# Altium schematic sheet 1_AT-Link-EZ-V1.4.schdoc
size 307 x 218 mm; Symbol: Artery_A4; Device: Artery_A4; @Project Name: AT-START-M416; @Page Count: 4; @Create Date: 2024-11-11; Company: Artery Technology; Drawed: SD; Version: 1.1; Page Size: A4; @Update Date: 2024-12-31; @Page No: 1; @Schematic Name: AT-START-M416-V1.1; @Page Name: AT-Link-EZ-V1.4; Title Block Position: 3; Width: 1170; Height: 825; Region Start: 1; X Region Count: 6; Y Region Count: 4; Blade Width: 10; @Board Name: AT-START-M416-V1.1; @Create Time: 14:16:05; @Update Time: 17:37:58
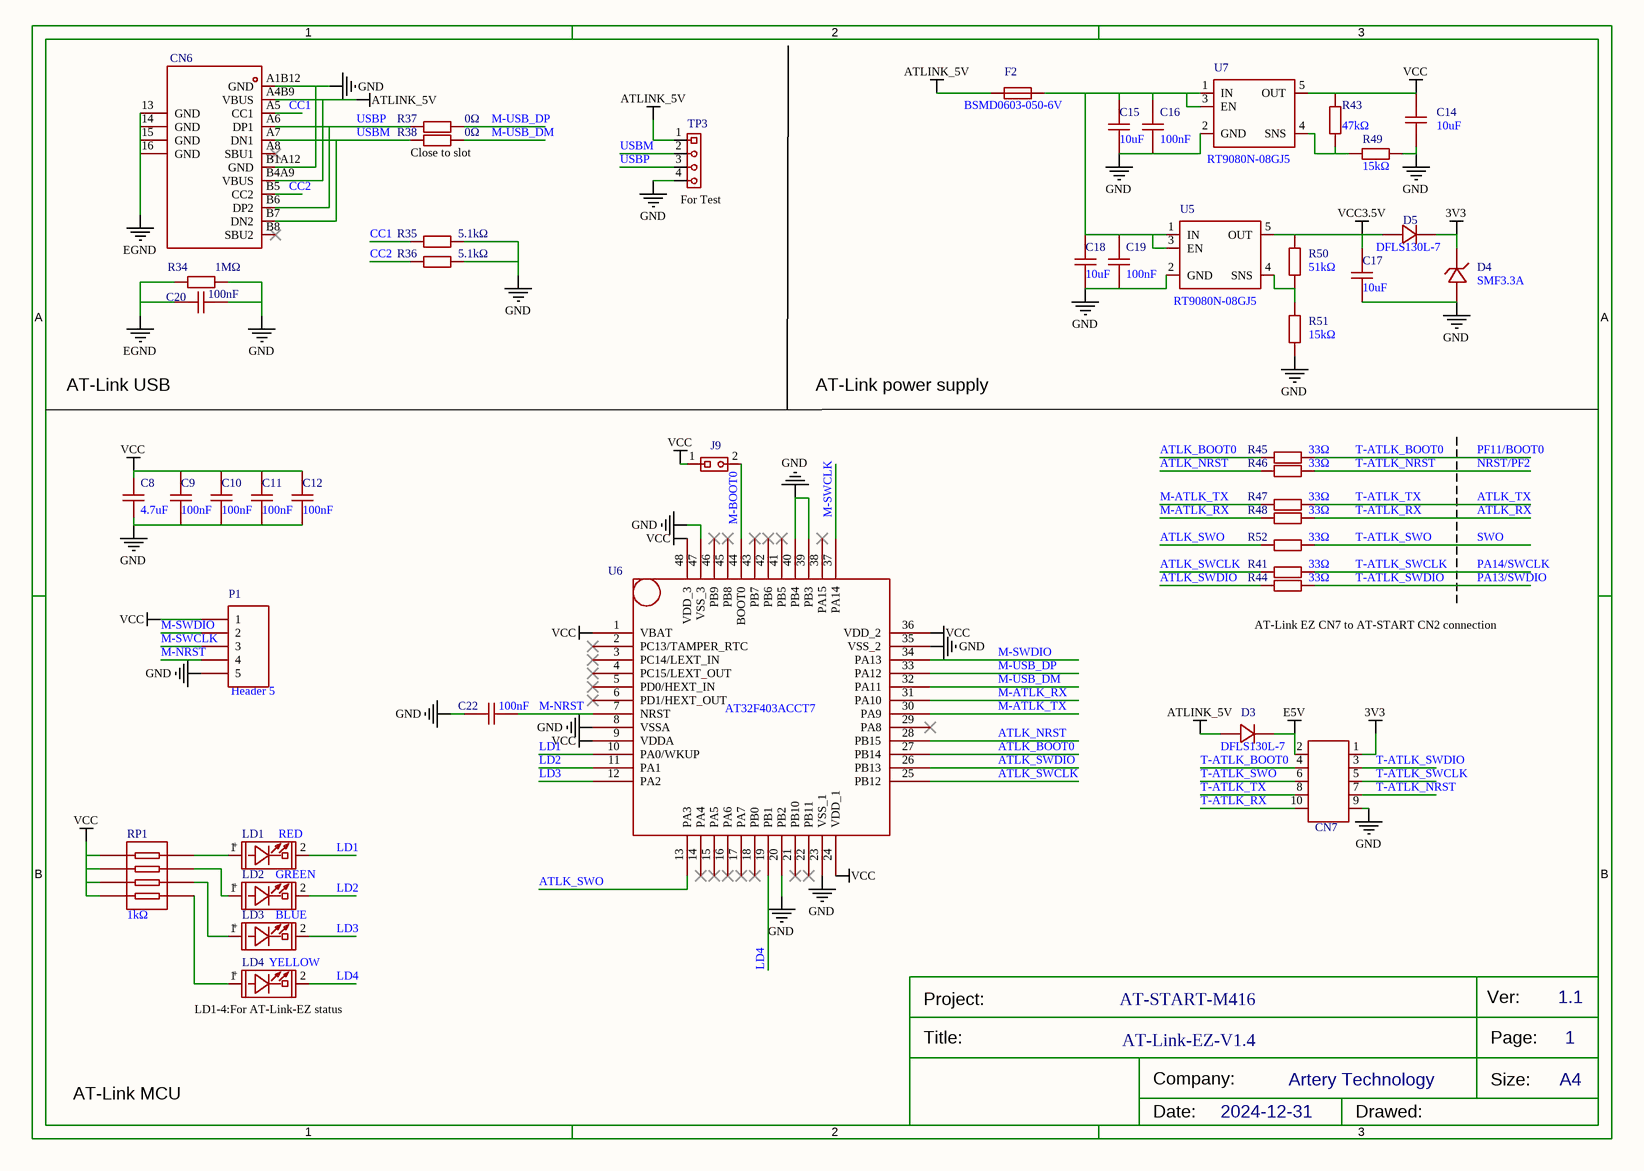
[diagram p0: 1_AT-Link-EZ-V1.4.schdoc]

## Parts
C8  4.7uF  [C0603]
C9  100nF  [C0603]
C10  100nF  [C0603]
C11  100nF  [C0603]
C12  100nF  [C0603]
C14  10uF  [C0603]
C15  10uF  [C0603]
C16  100nF  [C0603]
C17  10uF  [C0603]
C18  10uF  [C0603]
C19  100nF  [C0603]
C20  value 100nF  [C0603]
C22  100nF  [C0603]
CN6  (no value)  [USB-C-SMD_TYPEC-304-BCP16]
CN7  CON10  [HDR2X5]  (value not drawn)
D3  DFLS130L-7  [POWERDI-123_L2.8-W1.8-LS3.7-RD]
D4  SMF3.3A  [SOD-123FL_L2.8-W1.8-LS3.8-RD]
D5  DFLS130L-7  [POWERDI-123_L2.8-W1.8-LS3.7-RD]
F2  BSMD0603-050-6V  [F0603]
J9  1X2P_2.54M  [HDR1X2]  (value not drawn)
LD1  RED  [LED0603]
LD2  GREEN  [LED0603]
LD3  BLUE  [LED0603]
LD4  YELLOW  [LED0603]
P1  Header 5  [HDR1X5]
R34  value 1MΩ  [R0603]
R35  value 5.1kΩ  [R0603]
R36  value 5.1kΩ  [R0603]
R37  value 0Ω  [R0603]
R38  value 0Ω  [R0603]
R41  33Ω  [R0603]
R43  47kΩ  [R0603]
R44  33Ω  [R0603]
R45  33Ω  [R0603]
R46  33Ω  [R0603]
R47  33Ω  [R0603]
R48  33Ω  [R0603]
R49  15kΩ  [R0603]
R50  51kΩ  [R0603]
R51  15kΩ  [R0603]
R52  33Ω  [R0603]
RP1  1kΩ  [RES-ARRAY-SMD_0603-8P-L3.2-W1.6-BL]
TP3  1X4P_2.54F  [HDR1X4 - TOP]  (value not drawn)
U5  RT9080N-08GJ5  [SOT-23-5]
U6  AT32F403ACCT7  [LQFP48 - 2]
U7  RT9080N-08GJ5  [SOT-23-5]

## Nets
3V3: CN7.1 D4.1(C) D5.1
ATLINK_5V: CN6.A4B9(VBUS) CN6.B4A9(VBUS) D3.2 F2.1 TP3.1
E5V: CN7.2 D3.1
EGND: C20.2 CN6.13(GND) CN6.14(GND) CN6.15(GND) CN6.16(GND) R34.1
GND: C8.1 C9.1 C10.1 C11.1 C12.1 C14.1 C15.1 C16.1 C17.1 C18.1 C19.1 C20.1 C22.1 CN6.A1B12(GND) CN6.B1A12(GND) CN7.9 D4.2(A) P1.5 R34.2 R35.2 R36.2 R49.2 R51.2 TP3.4 U5.2(GND) U6.8(VSSA) U6.20(PB2) U6.23(VSS_1) U6.35(VSS_2) U6.39(PB3) U6.40(PB4) U6.47(VSS_3) U7.2(GND)
VCC: C8.2 C9.2 C10.2 C11.2 C12.2 C14.2 J9.1 P1.1 R43.1 RP1.1 RP1.2 RP1.3 RP1.4 U6.1(VBAT) U6.9(VDDA) U6.24(VDD_1) U6.36(VDD_2) U6.48(VDD_3) U7.5(OUT)
VCC3.5V: C17.2 D5.2 R50.1 U5.5(OUT)
ATLK_BOOT0: R45.1 U6.27(PB14)
ATLK_NRST: R46.1 U6.28(PB15)
ATLK_RX: CN7.10 R48.2  [also labelled T-ATLK_RX]
ATLK_SWCLK: R41.1 U6.25(PB12)
ATLK_SWDIO: R44.1 U6.26(PB13)
ATLK_SWO: R52.1 U6.13(PA3)
ATLK_TX: CN7.8 R47.2  [also labelled T-ATLK_TX]
CC1: CN6.A5(CC1) R35.1
CC2: CN6.B5(CC2) R36.1
LD1: LD1.2(CATHODE) U6.10(PA0/WKUP)
LD2: LD2.2(CATHODE) U6.11(PA1)
LD3: LD3.2(CATHODE) U6.12(PA2)
LD4: LD4.2(CATHODE) U6.19(PB1)
M-ATLK_RX: R48.1 U6.31(PA10)
M-ATLK_TX: R47.1 U6.30(PA9)
M-BOOT0: J9.2 U6.44(BOOT0)
M-NRST: C22.2 P1.4 U6.7(NRST)
M-SWCLK: P1.3 U6.37(PA14)
M-SWDIO: P1.2 U6.34(PA13)
M-USB_DM: R38.2 U6.32(PA11)
M-USB_DP: R37.2 U6.33(PA12)
NRST/PF2: CN7.7 R46.2  [also labelled T-ATLK_NRST]
PA13/SWDIO: CN7.3 R44.2  [also labelled T-ATLK_SWDIO]
PA14/SWCLK: CN7.5 R41.2  [also labelled T-ATLK_SWCLK]
PF11/BOOT0: CN7.4 R45.2  [also labelled T-ATLK_BOOT0]
SWO: CN7.6 R52.2  [also labelled T-ATLK_SWO]
USBM: CN6.A7(DN1) CN6.B7(DN2) R38.1 TP3.2
USBP: CN6.A6(DP1) CN6.B6(DP2) R37.1 TP3.3
NetC15_2: C15.2 C16.2 C18.2 C19.2 F2.2 U5.1(IN) U5.3(EN) U7.1(IN) U7.3(EN)
NetLD1_1: LD1.1(ANODE) RP1.8
NetLD2_1: LD2.1(ANODE) RP1.7
NetLD3_1: LD3.1(ANODE) RP1.6
NetLD4_1: LD4.1(ANODE) RP1.5
NetR43_2: R43.2 R49.1 U7.4(SNS)
NetR50_2: R50.2 R51.1 U5.4(SNS)

Not connected (* = marked no-connect by the designer): CN6 A8(SBU1)* B8(SBU2)*; U6 2(PC13/TAMPER_RTC)* 3(PC14/LEXT_IN)* 4(PC15/LEXT_OUT)* 5(PD0/HEXT_IN)* 6(PD1/HEXT_OUT)* 14(PA4)* 15(PA5)* 16(PA6)* 17(PA7)* 18(PB0)* 21(PB10)* 22(PB11)* 29(PA8)* 38(PA15)* 41(PB5)* 42(PB6)* 43(PB7)* 45(PB8)* 46(PB9)*

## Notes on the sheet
- (near R38) Close to slot
- (near TP3) For Test
- AT-Link USB
- AT-Link power supply
- AT-Link EZ CN7 to AT-START CN2 connection
- (near LD4) LD1-4:For AT-Link-EZ status
- AT-START-M416
- AT-Link MCU

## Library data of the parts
C8 = CL10A475KO8NNNC: Manufacturer: SAMSUNG(三星); Add into BOM: yes; Tolerance: ±10%; Voltage Rated: 16V; Temperature Coefficient: X5R; Origin Footprint 2: 0603; Origin Footprint 3: 0402; Origin Footprint 4: C2512; Origin Footprint 5: 1608[0603]; Origin Footprint 6: C1210
C9-C12 = CC0603KRX7R9BB104: Manufacturer: YAGEO(国巨); Add into BOM: yes; Tolerance: ±10%; Voltage Rated: 50V; Temperature Coefficient: X7R; Origin Footprint 2: 0603; Origin Footprint 3: 0402; Origin Footprint 4: C2512; Origin Footprint 5: 1608[0603]; Origin Footprint 6: C1210
C14 C15 C17 C18 = CL10A106KP8NNNC: Manufacturer: SAMSUNG(三星); Add into BOM: yes; Tolerance: ±10%; Voltage Rated: 10V; Temperature Coefficient: X5R
C16 C19 C20 C22 = CC0603KRX7R9BB104: Manufacturer: YAGEO(国巨); Add into BOM: yes; Tolerance: ±10%; Voltage Rated: 50V; Temperature Coefficient: X7R
CN6 = TYPEC-304-BCP16: Manufacturer: XUNPU(讯普); Add into BOM: yes; Connector Type: Type-C; Gender: 母座; Number of Contacts: 16.0; Number of Ports: 1; Mounting Sytle: 卧贴; Current Rating - Power (Max): 3A; Welding Temperature (Max): 260
CN7 = CON10: Symbol: CON10A_0; Add into BOM: yes
D3 D5 = DFLS130L-7: Manufacturer: DIODES(美台); Add into BOM: yes; Forward Voltage (Vf@If): 310mV@1A; Reverse Voltage (Vr): 30V; Average Rectified Current (Io): 1A; Origin Footprint: SOD-123
D4 = SMF3.3A_C2759873: Manufacturer: Leiditech(雷卯电子); Add into BOM: yes; Reverse Stand-Off Voltage (Vrwm): 3.3V; Maximum Clamping Voltage: 7.3V; Peak Pulse Current (Ipp)@10/1000us: 27.5A; Breakdown Voltage: 4.1V; Reverse Leakage Current (Ir): 500uA; Type: TVS; Origin Footprint: SOD-123
F2 = BSMD0603-050-6V: Manufacturer: BHFUSE(佰宏); Add into BOM: yes; Operating Voltage (Max): 6V; Current Rating (Max): 40A; Hold Current: 500mA; Trip Current: 1A; Power Dissipation: 500mW; Resistance - Initial (Ri) (Min): 100mΩ; Resistance - Post Trip (R1) (Max): 800mΩ; Maximum Time to Trip: 100ms; Origin Footprint: r0603
J9 = 1X2P_2.54M: Symbol: 1X2P,Male,DIP_2.54; Origin Footprint 2: SIP_2P; Add into BOM: yes; Check: true
LD1 = RED: Symbol: RED,SMD0603; Add into BOM: yes
LD2 = GREEN: Symbol: GREEN,SMD0603; Add into BOM: yes
LD3 = BLUE: Symbol: BLUE,SMD0603; Add into BOM: yes
LD4 = YELLOW: Symbol: YELLOW,SMD0603; Add into BOM: yes
P1 = Header 5: Add into BOM: yes
R34 = RC0603FR-071ML: Manufacturer: YAGEO(国巨); Add into BOM: yes; Tolerance: ±1%; Power(Watts): 100mW; Temperature Coefficient: ±100ppm/; Overload Voltage (Max): 75V
R35 R36 = 0603WAF5101T5E: Manufacturer: UNI-ROYAL(厚声); Add into BOM: yes; Tolerance: ±1%; Power(Watts): 1/10W; Temperature Coefficient: ±100ppm/; Overload Voltage (Max): 75V
R37 R38 = 0603WAF0000T5E: Manufacturer: UNI-ROYAL(厚声); Add into BOM: yes; Tolerance: ±1%; Power(Watts): 1/10W; Overload Voltage (Max): 75V
R41 R44-R48 R52 = 0603WAF330JT5E: Manufacturer: UNI-ROYAL(厚声); Add into BOM: yes; Tolerance: ±1%; Power(Watts): 100mW; Overload Voltage (Max): 75V; Temperature Coefficient: ±100ppm/℃
R43 = 0603WAF4702T5E: Manufacturer: UNI-ROYAL(厚声); Add into BOM: yes; Tolerance: ±1%; Power(Watts): 100mW; Overload Voltage (Max): 75V; Temperature Coefficient: ±100ppm/℃
R49 R51 = 0603WAF1502T5E: Manufacturer: UNI-ROYAL(厚声); Add into BOM: yes; Tolerance: ±1%; Power(Watts): 100mW; Overload Voltage (Max): 75V; Temperature Coefficient: ±100ppm/℃
R50 = 0603WAF5102T5E: Manufacturer: UNI-ROYAL(厚声); Add into BOM: yes; Tolerance: ±1%; Power(Watts): 100mW; Overload Voltage (Max): 75V; Temperature Coefficient: ±100ppm/℃
RP1 = 4D03WGJ0102T5E: Manufacturer: UNI-ROYAL(厚声); Add into BOM: yes; Number of Resistors: 4; Tolerance: ±5%; Power(Watts): 62.5mW; Temperature Coefficient: ±200ppm/℃; Origin Footprint: RP_4-0603
TP3 = 1X4P_2.54F: Convert to PCB: yes
U5 U7 = RT9080N-08GJ5: Add into BOM: yes
U6 = AT32F403CGT6: Symbol: LQFP48&QFN48; Add into BOM: yes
